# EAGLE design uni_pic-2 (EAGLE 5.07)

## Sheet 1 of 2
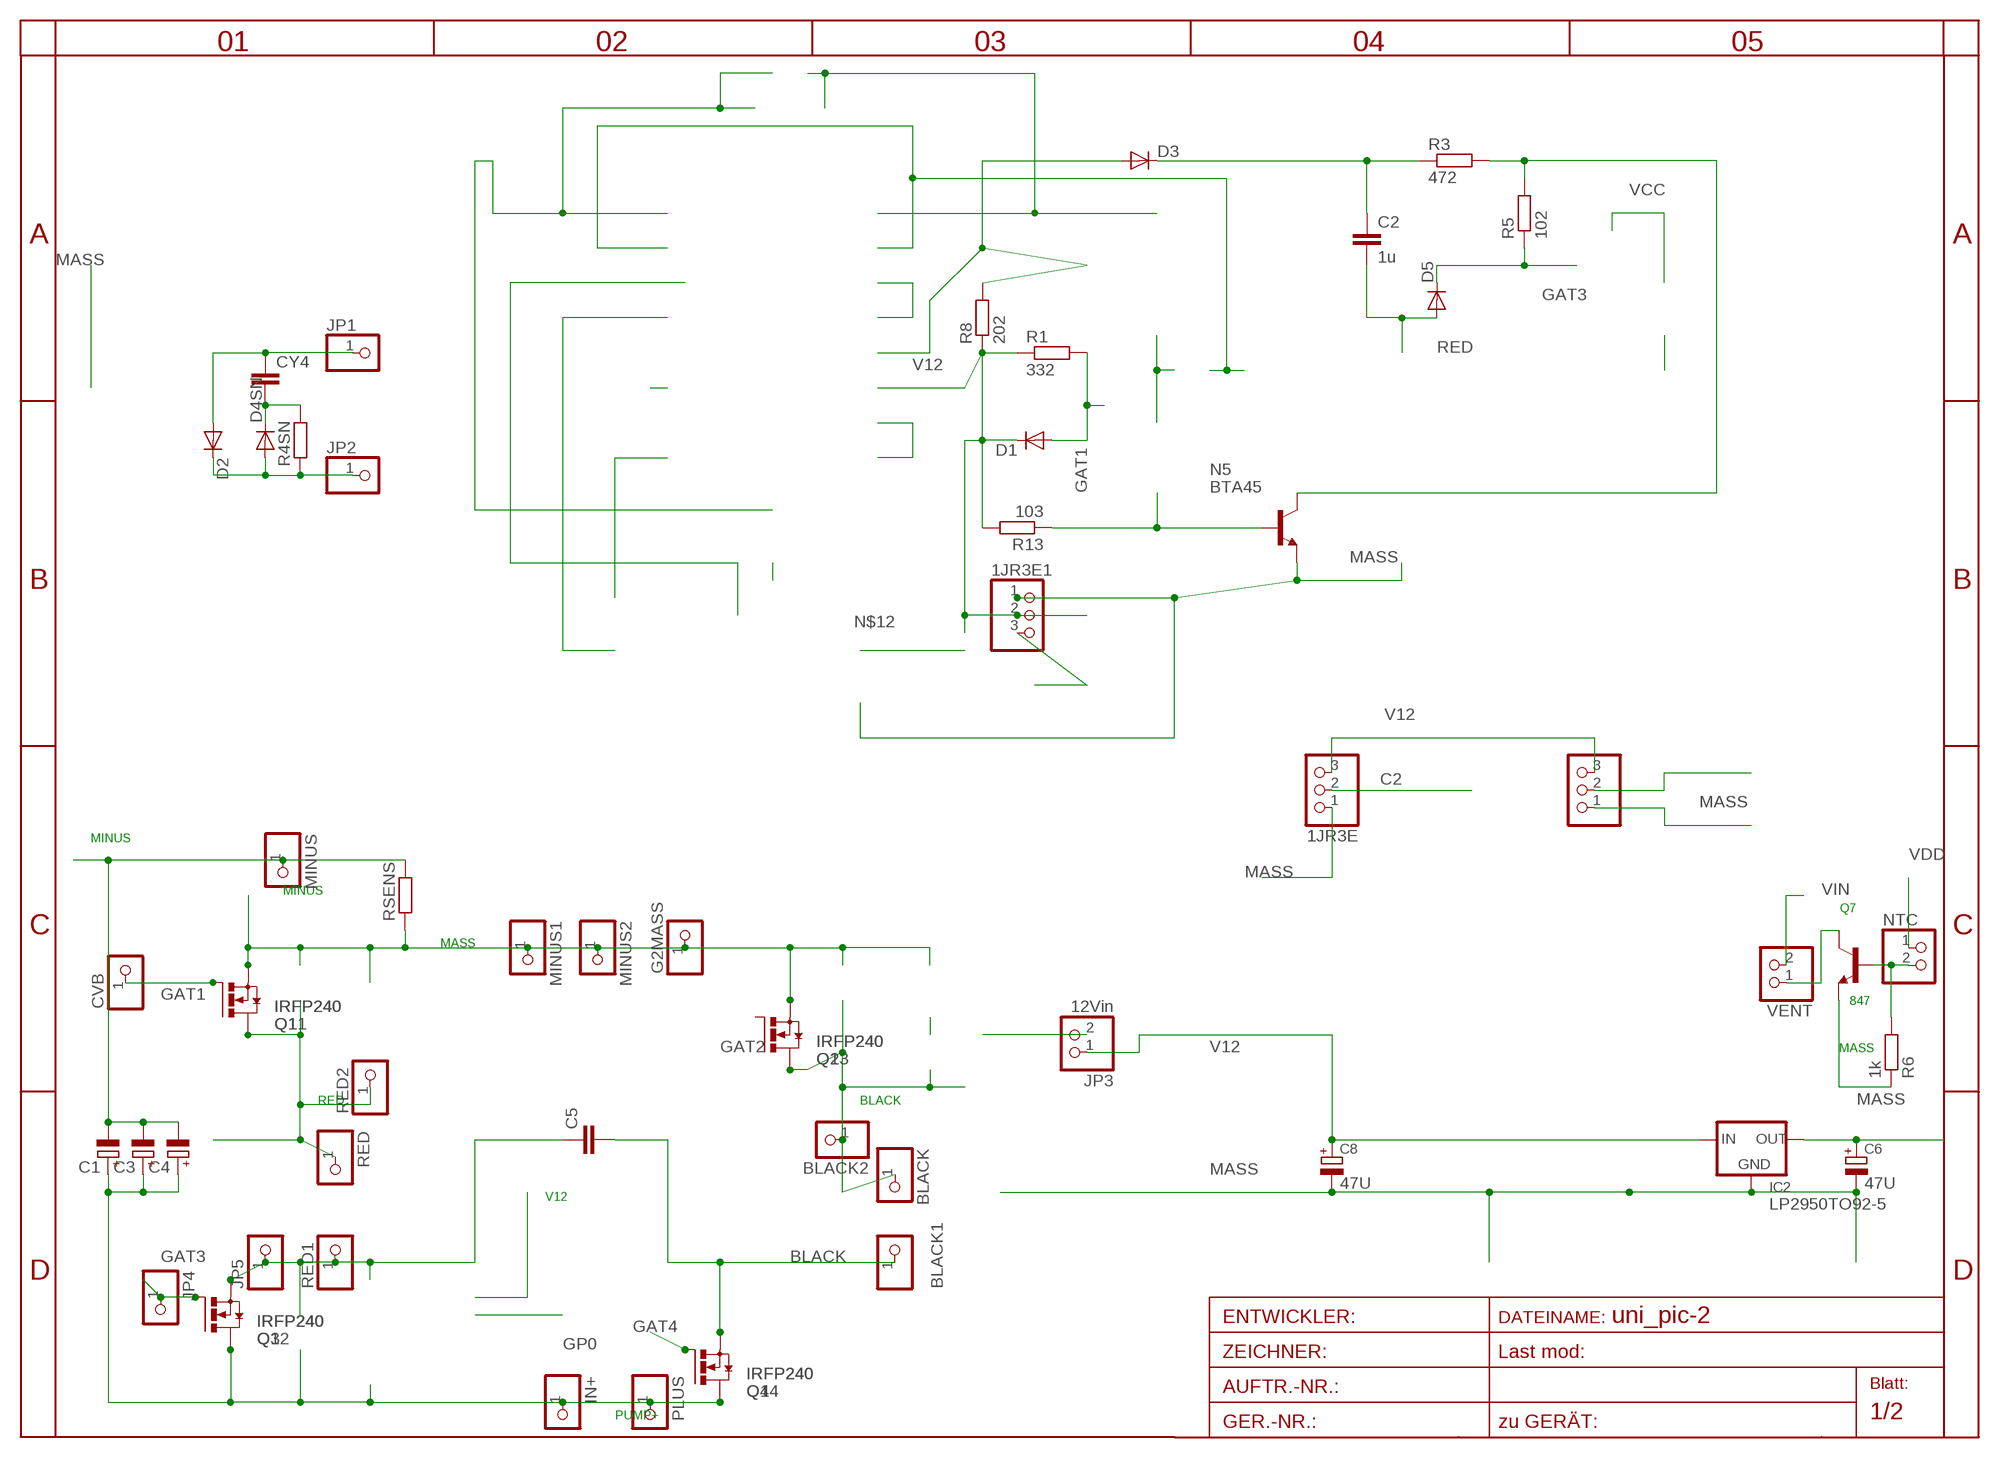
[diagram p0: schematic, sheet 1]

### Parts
1JR3E  PINHD-1X3  [1X03]
1JR3E1  PINHD-1X3  [1X03]
2JR4E3  PINHD-1X3  [1X03]
BLACK  PINHD-1X12MM3  [1X2MM3]
BLACK1  PINHD-1X12MM3  [1X2MM3]
BLACK2  PINHD-1X12MM3  [1X2MM3]
C1  CPOL-EUE5-13  [E5-13]
C2  1u  C-EUC1206  [C1206]
C3  CPOL-EUE5-13  [E5-13]
C4  CPOL-EUE5-13  [E5-13]
C5  C-EU075-032X103  [C075-032X103]
C6  47U  CPOL-EUE2.5-6  [E2,5-6]
C8  47U  CPOL-EUE2.5-6  [E2,5-6]
CVB  PINHD-1X11MM0  [1X1MM0]
CY4  CXXC10B5  [XC10B5]
D1  DIODE-MINIMELF  [MINIMELF]
D2  DIODE-SMC  [SMC]
D3  DIODE-SMA-DO214  [SMA-DO214AC]
D4SN  DIODE-P1-10  [P1-10]
D5  DIODE-MINIMELF  [MINIMELF]
G2MASS  PINHD-1X11MM0  [1X1MM0]
IC2  LP2950TO92-5  [T092-5]
IN+  PINHD-1X12MM3  [1X2MM3]
JP1  PINHD-1X11MM0  [1X1MM0]
JP2  PINHD-1X11MM0  [1X1MM0]
JP3  12Vin  PINHD-1X2STR  [1X02]
JP4  PINHD-1X11MM0  [1X1MM0]
JP5  PINHD-1X11MM0  [1X1MM0]
MINUS  PINHD-1X12MM3  [1X2MM3]
MINUS1  PINHD-1X12MM3  [1X2MM3]
MINUS2  PINHD-1X12MM3  [1X2MM3]
N5  BTA45  SMBTA45HV  [SOT23HV]
NTC  PINHD-1X2STR  [1X02]
PLUS  PINHD-1X12MM3  [1X2MM3]
Q1  IRFP240  [TO247BV]
Q2  IRFP240  [TO247BV]
Q3  IRFP240  [TO247BV]
Q4  IRFP240  [TO247BV]
Q7  847  BC847ALT1SMD  [SOT23]
Q11  IRFP240  [TO247BV]
Q12  IRFP240  [TO247BV]
Q13  IRFP240  [TO247BV]
Q14  IRFP240  [TO247BV]
R1  332  R-EU_R0805  [R0805]
R3  472  R-EU_R0805  [R0805]
R4SN  R-EU_0207/10  [0207/10]
R5  102  R-EU_R1206  [R1206]
R6  1k  R-EU_R0805  [R0805]
R8  202  R-EU_R0805  [R0805]
R13  103  R-EU_0207/15  [0207/15]
RED  PINHD-1X12MM3  [1X2MM3]
RED1  PINHD-1X12MM3  [1X2MM3]
RED2  PINHD-1X12MM3  [1X2MM3]
RSENS  R-EU_0204/7  [0204/7]
VENT  PINHD-1X2STR  [1X02]

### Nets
BLACK: BLACK1.1 BLACK2.1 BLACK.1 C5.2 Q2.D Q4.S Q13.D Q14.S
C1: 2JR4E3.2 ; also sheet 2
C2: 1JR3E1.2 1JR3E.2 D1.C R1.1 R8.1 R13.2 ; also sheet 2
DRAIN: D2.C D4SN.A JP2.1 R4SN.1
GAT1: CVB.1 D1.A Q1.G Q11.G R1.2
GAT2: Q2.G Q13.G
GAT3: D5.C JP4.1 Q3.G Q12.G R5.1
GAT4: Q4.G Q14.G
MASS: 1JR3E1.1 1JR3E.1 2JR4E3.1 C6.- C8.- G2MASS.1 IC2.2(GND) JP3.2 MINUS1.1 MINUS2.1 N5.2(E) Q1.S Q2.S Q7.2(E) Q11.S Q13.S R6.1 RSENS.1 ; also sheet 2
MINUS: C1.- C3.- C4.- MINUS.1 RSENS.2
N$4: C2.1 D3.K(C) R3.1
N$8: N5.3(C) R3.2 R5.2
N$9: NTC.2 Q7.1(B) R6.2
N$10: Q7.3(C) VENT.1
N$17: N5.1(B) R13.1
PUMP+: C1.+ C3.+ C4.+ IN+.1 PLUS.1 Q3.D Q4.D Q12.D Q14.D ; also sheet 2
RED: C2.2 C5.1 D5.A JP5.1 Q1.D Q3.S Q11.D Q12.S RED1.1 RED2.1 RED.1
SNUB2: CY4.2 D4SN.C R4SN.2
SOURCE: CY4.1 D2.A JP1.1
V12: 1JR3E1.3 1JR3E.3 2JR4E3.3 C8.+ D3.A IC2.3(IN) JP3.1 R8.2
VDD: C6.+ IC2.1(OUT) NTC.1 ; also sheet 2
VIN: VENT.2

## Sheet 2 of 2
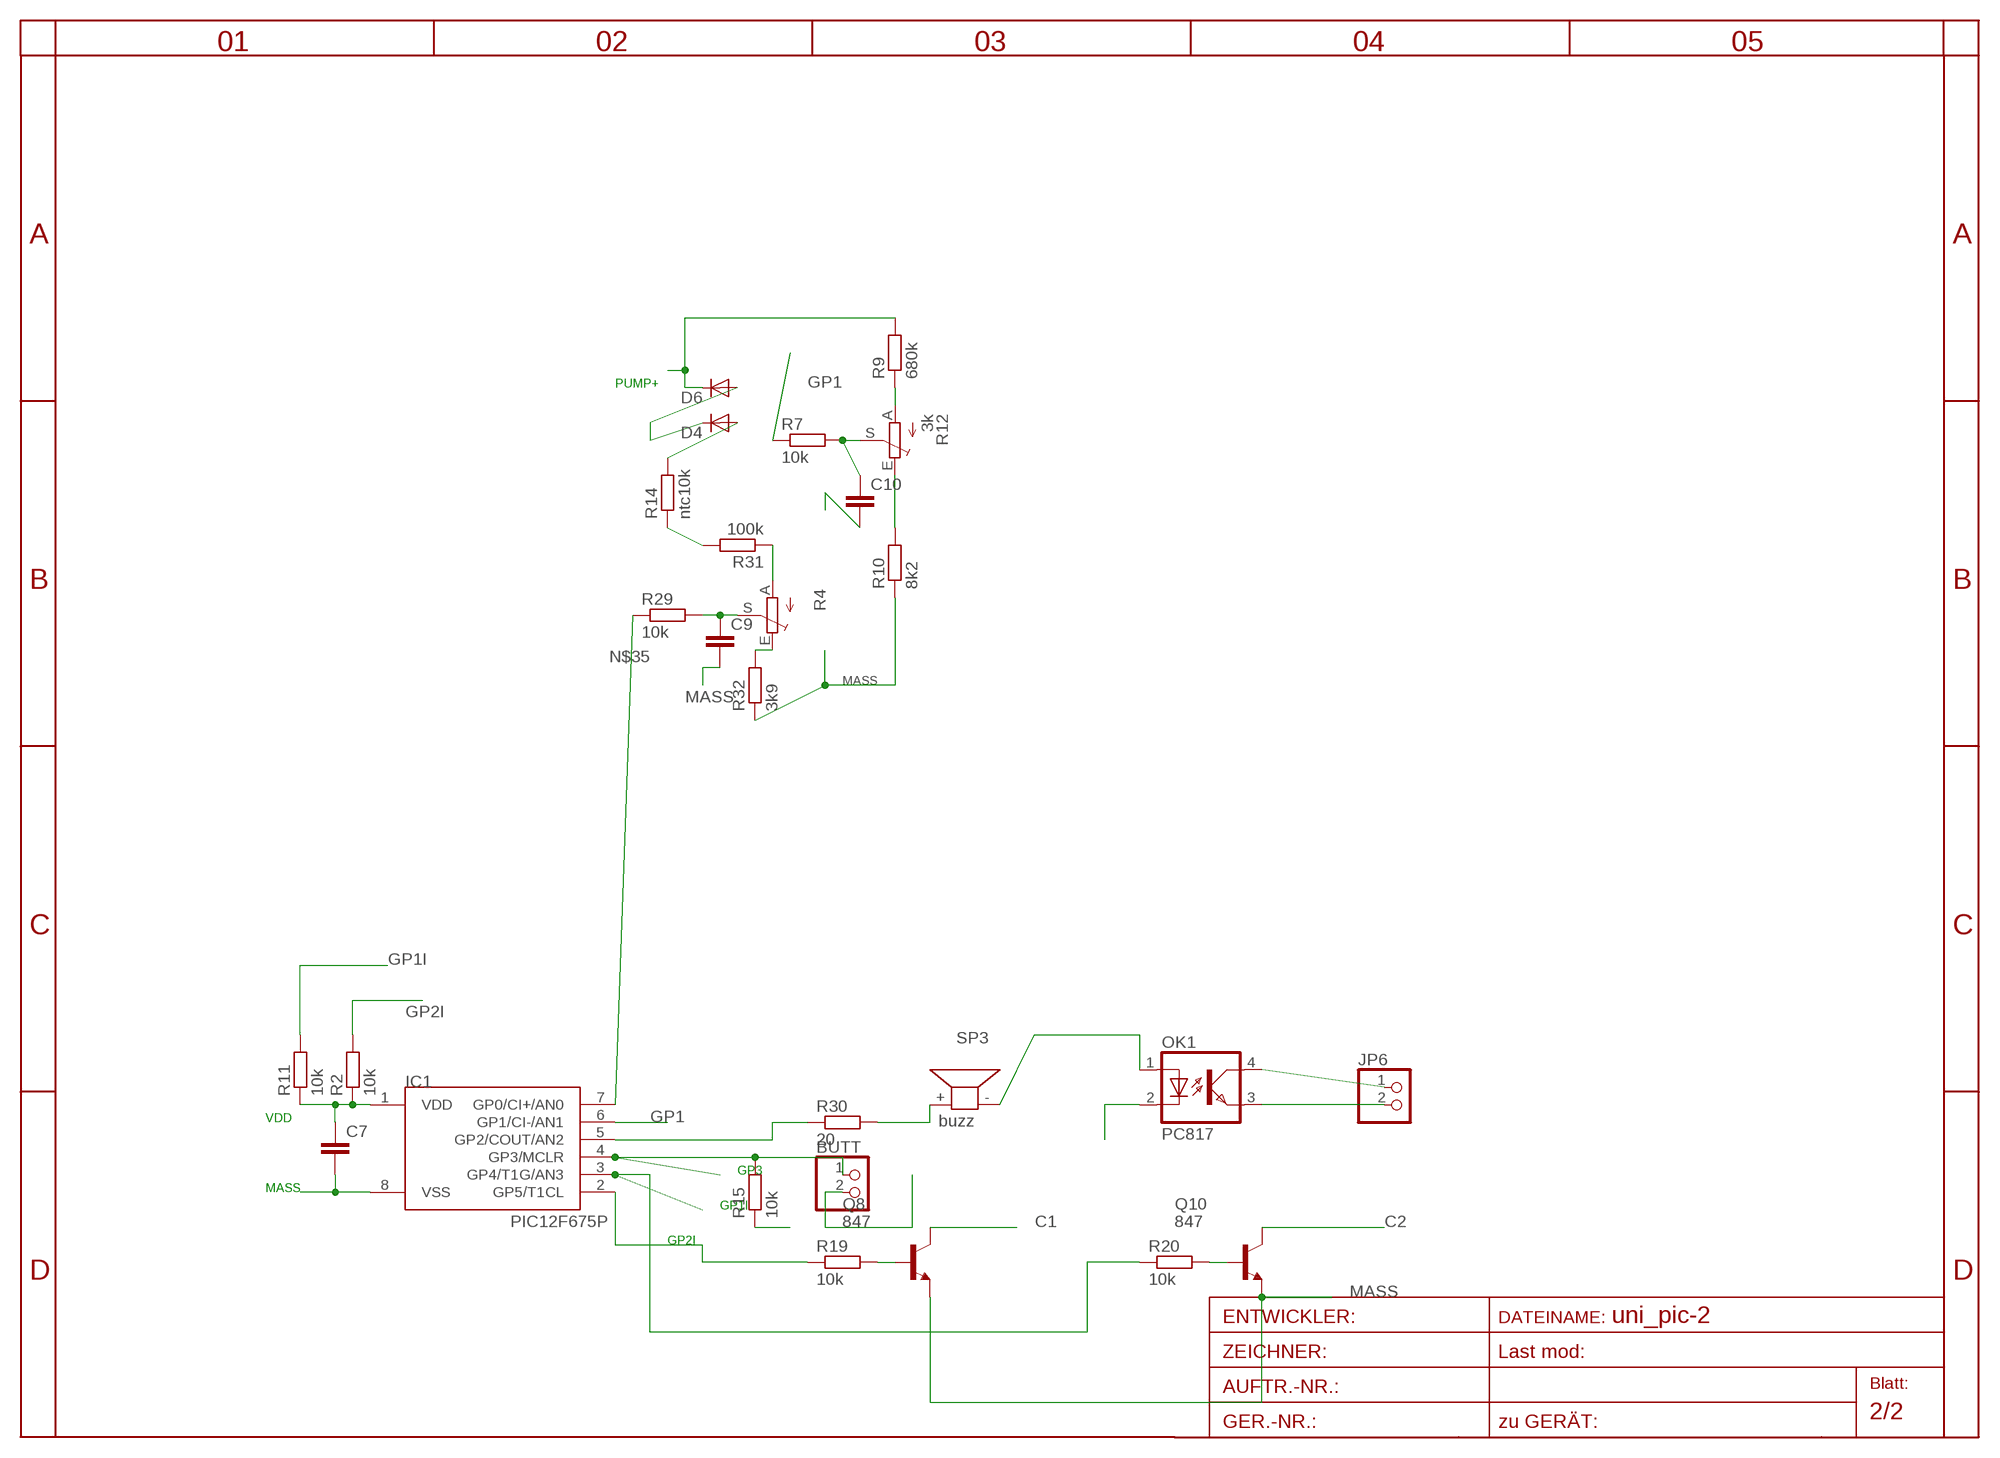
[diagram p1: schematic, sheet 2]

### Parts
BUTT  PINHD-1X2STR  [1X02]
C7  C-EUC0805  [C0805]
C9  C-EUC0805  [C0805]
C10  C-EUC0805  [C0805]
D4  DIODE-MINIMELF  [MINIMELF]
D6  DIODE-MINIMELF  [MINIMELF]
IC1  PIC12F675P  [DIL8]
JP6  PINHD-1X2STR  [1X02]
OK1  PC817  [DIL04]
Q8  847  BC847ALT1SMD  [SOT23]
Q10  847  BC847ALT1SMD  [SOT23]
R2  10k  R-EU_R0805  [R0805]
R4  TRIM_EU-CA6V  [CA6V]
R7  10k  R-EU_R0805  [R0805]
R9  680k  R-EU_0207/30  [0207/30]
R10  8k2  R-EU_R0805  [R0805]
R11  10k  R-EU_R0805  [R0805]
R12  3k  TRIM_EU-CA6V  [CA6V]
R14  ntc10k  R-EU_0204/5  [0204/5]
R15  10k  R-EU_R0805  [R0805]
R19  10k  R-EU_R0805  [R0805]
R20  10k  R-EU_R0805  [R0805]
R29  10k  R-EU_R0805  [R0805]
R30  20  R-EU_R0805  [R0805]
R31  100k  R-EU_0207/22  [0207/22]
R32  3k9  R-EU_R0805  [R0805]
SP3  buzz  KSS12017MM  [KSS1202]

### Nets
C1: Q8.3(C) ; also sheet 1
C2: Q10.3(C) ; also sheet 1
GP0I: IC1.5(GP2/COUT/AN2) R30.1
GP1: IC1.6(GP1/CI-/AN1) R7.1
GP1I: IC1.3(GP4/T1G/AN3) R11.2 R20.1
GP2I: IC1.2(GP5/T1CL) R2.2 R19.1
GP3: BUTT.1 IC1.4(GP3/MCLR) R15.2
MASS: BUTT.2 C7.2 C9.2 C10.2 IC1.8(VSS) OK1.2(C) Q8.2(E) Q10.2(E) R10.1 R32.1 ; also sheet 1
N$1: R4.A R31.1
N$5: JP6.2 OK1.3(EMIT)
N$7: D4.C D6.A
N$19: C9.1 R4.S R29.2
N$22: Q10.1(B) R20.2
N$24: R14.1 R31.2
N$26: R4.E R32.2
N$27: D4.A R14.2
N$28: Q8.1(B) R19.2
N$29: R10.2 R12.E
N$30: R9.1 R12.A
N$31: C10.1 R7.2 R12.S
N$32: JP6.1 OK1.4(COL)
N$33: R30.2 SP3.+
N$34: OK1.1(A) SP3.-
N$35: IC1.7(GP0/CI+/AN0) R29.1
PUMP+: D6.C R9.2 ; also sheet 1
VDD: C7.1 IC1.1(VDD) R2.1 R11.1 R15.1 ; also sheet 1

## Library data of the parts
1JR3E 1JR3E1 2JR4E3 = pinhead:PINHD-1X3: PIN HEADER
BLACK BLACK1 BLACK2 CVB G2MASS IN+ JP1 JP2 JP4 JP5 MINUS MINUS1 MINUS2 PLUS RED RED1 RED2 = pinhead:PINHD-1X1: PIN HEADER
BUTT JP3 JP6 NTC VENT = pinhead:PINHD-1X2: PIN HEADER
C1 C3 C4 = rcl:CPOL-EU: POLARIZED CAPACITOR, European symbol
C2 C5 C7 C9 C10 = rcl:C-EU: CAPACITOR, European symbol
C6 C8 = rcl-2:CPOL-EU: POLARIZED CAPACITOR, European symbol
CY4 = rcl:CX: X CAPACITOR
D1-D4 D4SN D5 D6 = diode:DIODE-: DIODE
IC1 = microchip-5:PIC12F6*: uPC nW 1k Program Flash memory 2x Timer Comparator 10b A/D converter/ 4xIN
IC2 = v-reg:LP2950?*: Source: http://cache.national.com/ds/LP/LP2950.pdf
N5 = transistor-npn:SMBTA45
OK1 = optocoupler:PC817: SHARP OPTO COUPLER
Q1-Q4 Q11-Q14 = transistor-power:IRFP240: HEXFET Power MosFet Source: http://www.irf.com/
Q7 Q8 Q10 = transistor-npn:BC847*: NPN Transistor
R1 R3 R4SN R5 R6 R8 R13 RSENS = rcl:R-EU_: RESISTOR, European symbol
R2 R7 R9-R11 R14 R15 R19 R20 R29-R32 = rcl-2:R-EU_: RESISTOR, European symbol
R4 R12 = pot:TRIM_EU-: POTENTIOMETER
SP3 = buzzer:KSS1201: SPEAKER

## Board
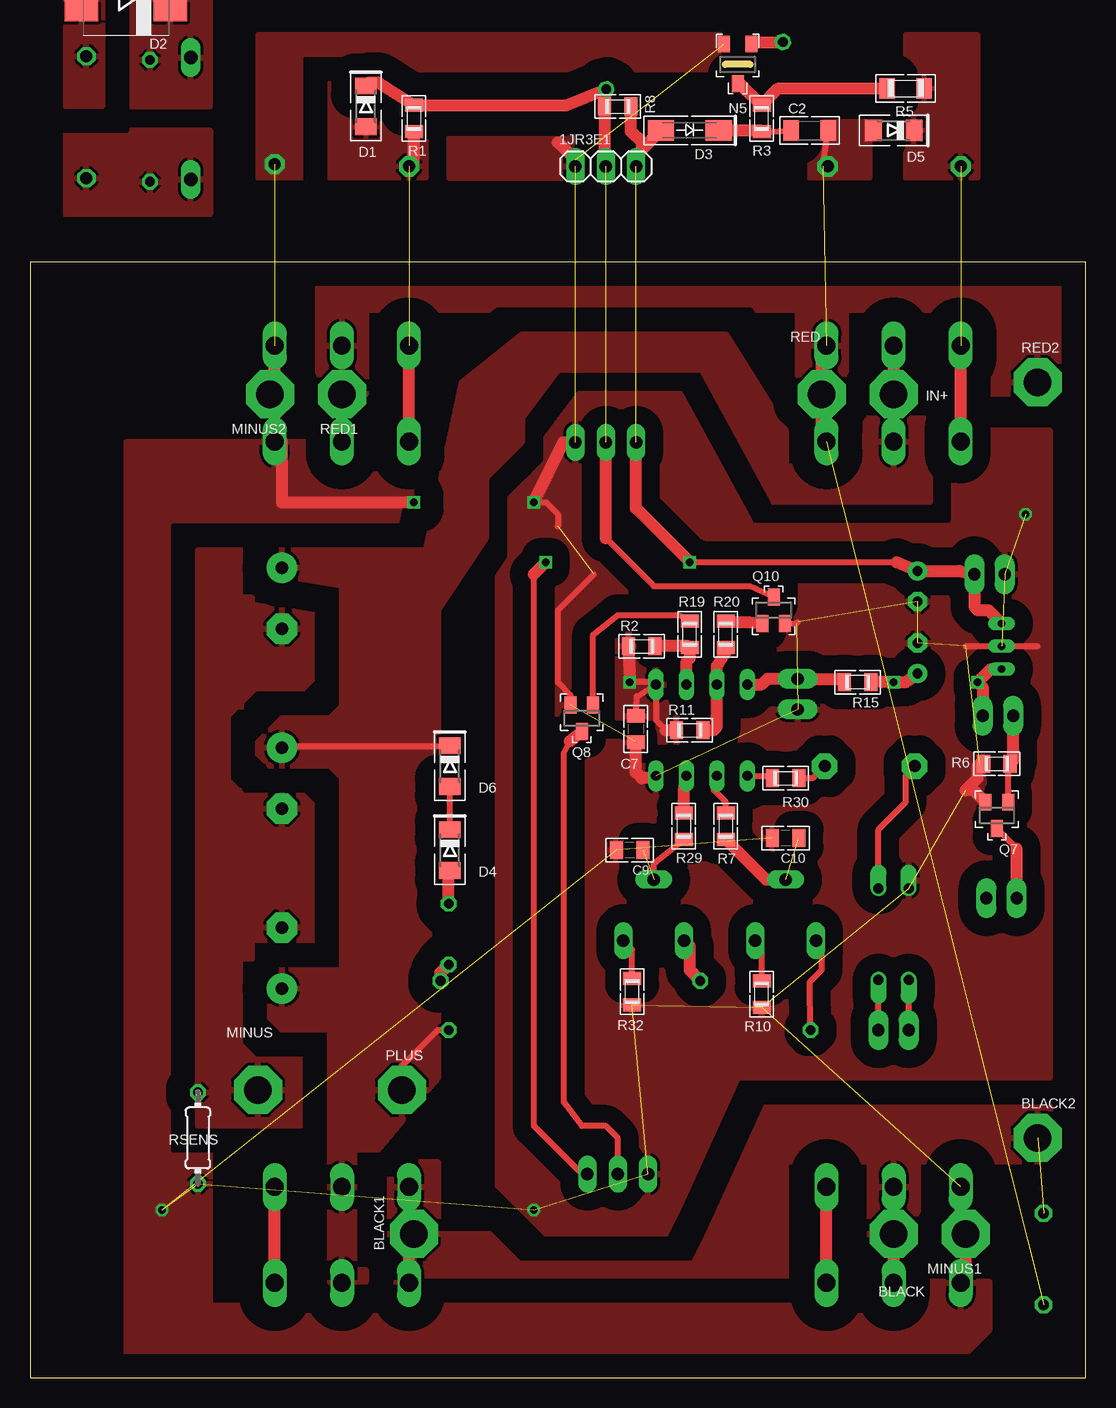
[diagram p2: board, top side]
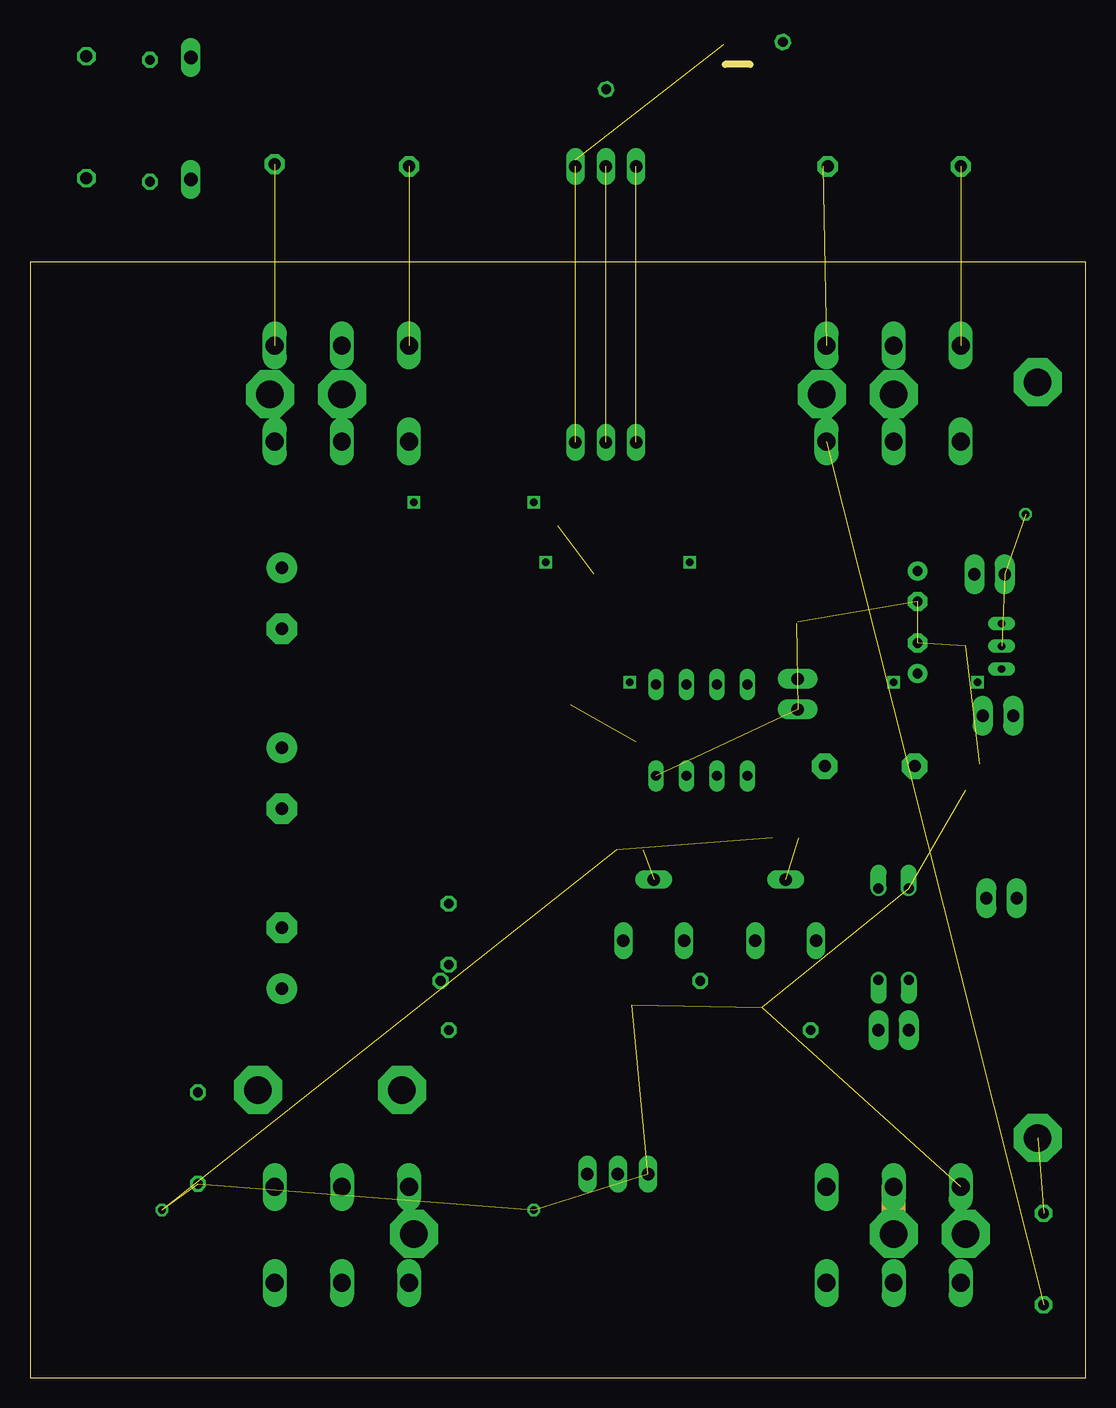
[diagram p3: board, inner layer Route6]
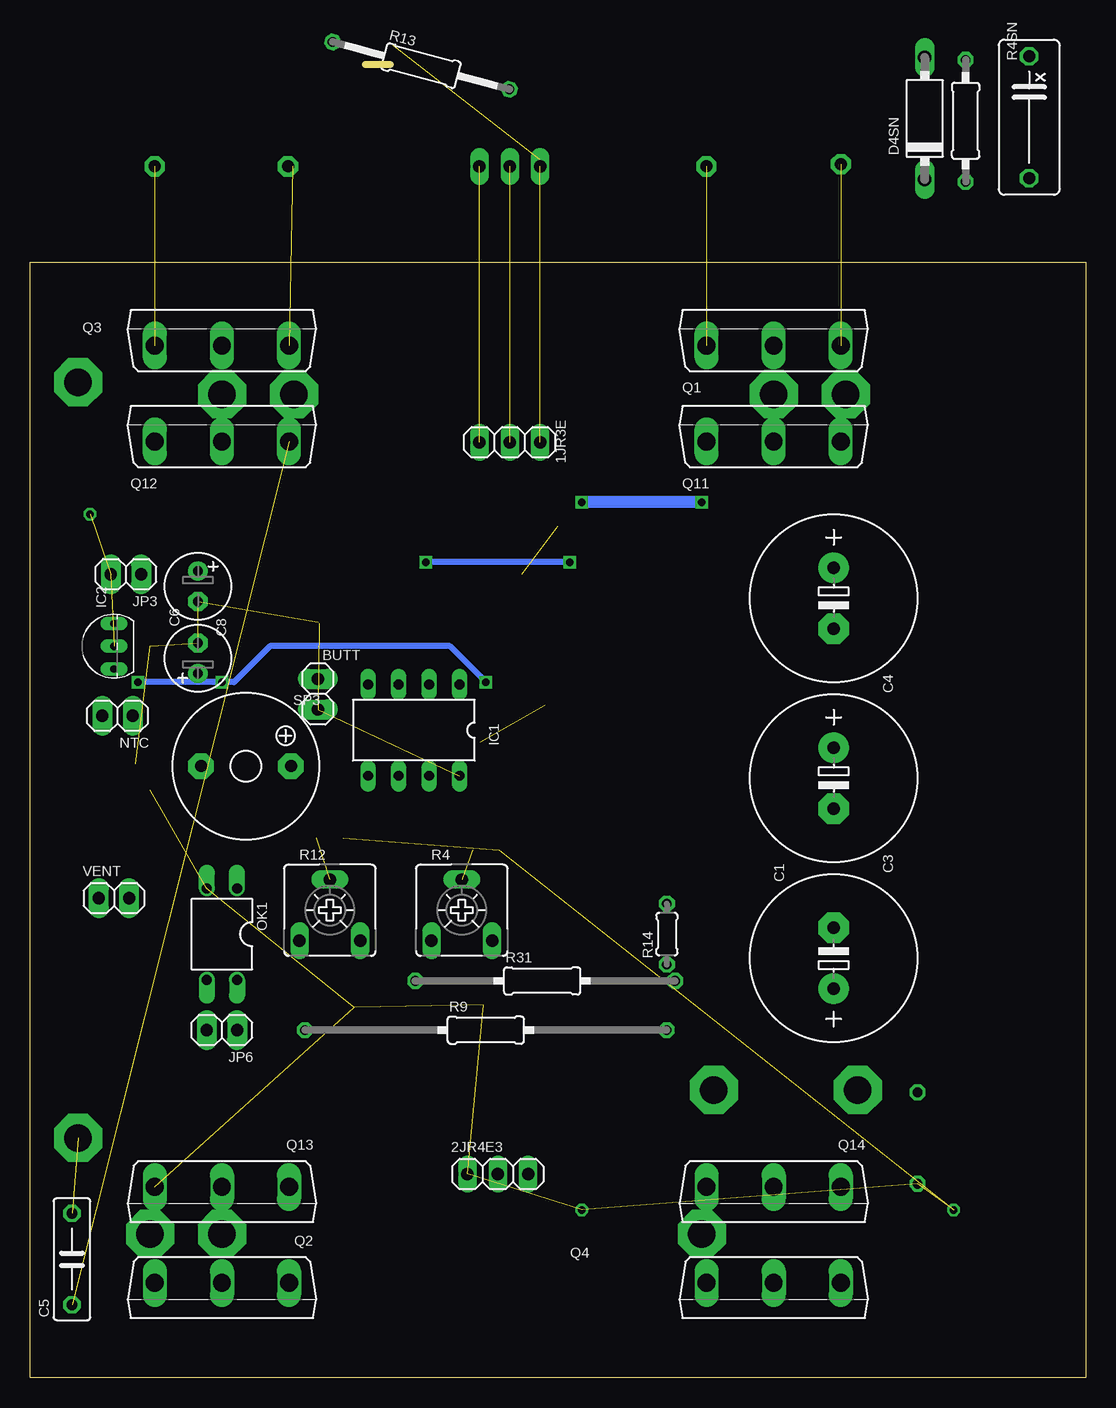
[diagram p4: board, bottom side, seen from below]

Size 88 x 93 mm. Coordinates in mm from the lower left corner, seen from the top.
Outline: 0,0 88,0 88,93 0,93 0,0
Copper layers (1*16): Top 0.035mm / dielectric 1.5mm / Bottom 0.035mm
Design rules "default *": minimum track width 10mil, minimum drill 20mil, track to track 8mil, track to pad 8mil, pad to pad 8mil, via to via 8mil, smd to smd 8mil, copper to edge 40mil, drill to drill 8mil, minimum pad ring 10mil, minimum via ring 8mil, stop-mask expansion 4mil, vias tented up to drill 0mil, thermal gap 10mil

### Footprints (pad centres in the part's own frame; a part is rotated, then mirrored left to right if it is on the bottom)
1X03 = drill 1.016 long: 1 -2.54,0; 2 0,0; 3 2.54,0
1X2MM3 = drill 2.3 pad 4 octagon: 1 0,0
1X02 = drill 1.016 pad 1.676 long: 1 -1.27,0; 2 1.27,0
E5-13 = drill 1.016 pad 2.54 round: + -2.54,0 | drill 1.016 pad 2.54 octagon: - 2.54,0
C1206 = smd 1.3 x 1.7: 1 -1.55,0; 2 1.55,0
C075-032X103 = drill 0.914 octagon: 1 -3.81,0; 2 3.81,0
E2,5-6 = drill 0.813 pad 1.6 round: + -1.27,0 | drill 0.813 pad 1.6 octagon: - 1.27,0
C0805 = smd 1.1 x 1.5: 1 -1.1,0; 2 1.1,0
1X1MM0 = drill 1 pad 1.676 octagon: 1 0,0
XC10B5 = drill 1.016 octagon: 1 -5.08,0; 2 5.08,0
MINIMELF = smd 1.4 x 1.8: A 1.7,0; C -1.7,0
SMC = smd 2.8 x 3.8: A 3.7,0; C -3.7,0
SMA-DO214AC = smd 2.2 x 1.7: A 2.4,0; K -2.4,0
P1-10 = drill 1.118 long: A 5.08,0; C -5.08,0
DIL8 = drill 0.8 long: 1 -3.81,-3.81; 2 -1.27,-3.81; 3 1.27,-3.81; 4 3.81,-3.81; 5 3.81,3.81; 6 1.27,3.81; 7 -1.27,3.81; 8 -3.81,3.81
T092-5 = drill 0.6 pad 0.813 long: 1 -1.905,0; 2 0,0; 3 1.905,0
SOT23HV = smd 1 x 1.4: 1 -1.15,-1.7; 2 1.15,-1.7; 3 0,1.6
DIL04 = drill 0.813 offset: 1 -1.27,-3.81; 2 1.27,-3.81; 3 1.27,3.81; 4 -1.27,3.81
TO247BV = drill 1.499 long: D 0,-2.921; G -5.588,-2.921; S 5.588,-2.921
SOT23 = smd 1 x 1.4: 1 -0.95,-1.1; 2 0.95,-1.1; 3 0,1.1
R0805 = smd 1.1 x 1.5: 1 -1.1,0; 2 1.1,0
CA6V = drill 1.016 long: A -2.54,-2.54; E 2.54,-2.54; S 0,2.54
0207/10 = drill 0.813 octagon: 1 -5.08,0; 2 5.08,0
R1206 = smd 1.3 x 1.7: 1 -1.55,0; 2 1.55,0
0207/30 = drill 0.813 octagon: 1 -15.08,0; 2 15.08,0
0207/15 = drill 0.813 octagon: 1 -7.62,0; 2 7.62,0
0204/5 = drill 0.8 pad 1.27 octagon: 1 -2.54,0; 2 2.54,0
0207/22 = drill 0.813 octagon: 1 -10.58,0; 2 11.08,0
0204/7 = drill 0.813 octagon: 1 -3.81,0; 2 3.81,0
KSS1202 = drill 1 pad 2.159 octagon: + 3.75,0; - -3.75,0

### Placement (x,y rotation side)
1JR3E  48,78 180 bottom
1JR3E1  48,101 0 top  (outside the outline)
2JR4E3  49,17 0 bottom
BLACK  72,12 180 top
BLACK1  32,12 90 top
BLACK2  84,20 0 top
BUTT  64,57 270 bottom
C1  21,35 90 bottom
C2  65,104 0 top  (outside the outline)
C3  21,50 270 bottom
C4  21,65 270 bottom
C5  84.5,9.9 90 bottom
C6  74,60 90 bottom
C7  50.5,54.1 270 top
C8  74,66 270 bottom
C9  50,44 180 top
C10  63,45 180 top
CVB  31.6,101 0 top  (outside the outline)
CY4  not placed on the board
D1  28,106 270 top  (outside the outline)
D2  not placed on the board
D3  55,104 180 top  (outside the outline)
D4  35,44 270 top
D4SN  not placed on the board
D5  not placed on the board
D6  35,51 270 top
G2MASS  not placed on the board
IC1  56,54 180 bottom
IC2  81,61 90 bottom
IN+  72,82 0 top
JP1  not placed on the board
JP2  not placed on the board
JP3  80,67 180 bottom
JP4  not placed on the board
JP5  66.5,101 180 top  (outside the outline)
JP6  72,29 180 bottom
MINUS  19,24 0 top
MINUS1  78,12 180 top
MINUS2  20,82 180 top
N5  59,109.5 180 top  (outside the outline)
NTC  80.7,55.2 180 bottom
OK1  72,37 180 bottom
PLUS  31,24 0 top
Q1  26,89 0 bottom
Q2  72,5 180 bottom
Q3  72,89 0 bottom
Q4  26,5 180 bottom
Q7  80.6,46.9 180 top
Q8  46,55 180 top
Q10  62,64 0 top
Q11  26,81 0 bottom
Q12  72,81 0 bottom
Q13  72,13 180 bottom
Q14  26,13 180 bottom
R1  32,105 270 top  (outside the outline)
R2  51,61 0 top
R3  61,105 90 top  (outside the outline)
R4  52,39 0 bottom
R4SN  not placed on the board
R5  73,107.5 180 top  (outside the outline)
R6  80.6,51.2 0 top
R7  58,46 270 top
R8  49,106 0 top  (outside the outline)
R9  50,29 0 bottom
R10  61,32 90 top
R11  55,54 0 top
R12  63,39 0 bottom
R13  55.4,109.4 345 bottom  (outside the outline)
R14  34.9,37 90 bottom
R15  69,58 180 top
R19  55,62 90 top
R20  58,62 90 top
R29  54.5,46 270 top
R30  63,50 0 top
R31  45.3,33.1 0 bottom
R32  50.2,32.2 90 top
RED  66,82 0 top
RED1  26,82 180 top
RED2  84,83 0 top
RSENS  14,20 90 top
SP3  70,51 0 bottom
VENT  81,40 0 bottom

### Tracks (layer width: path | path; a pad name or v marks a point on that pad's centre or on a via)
BLACK  (1 unrouted)
  Top 1: Q14.S 31.59,11.41 32,11 BLACK1.1 31.59,11.59 Q4.S | Q2.D BLACK.1
  Route6 2: BLACK.1 Q13.D
  pour Top (isolate 2, rank 4): 30,18 34,18 34,12 55,12 61,24 85,24 85,18 74,18 74,10 70,10 70,18 63,18 63,8 30,8
C1
  Top 0.5: 2JR4E3.2 49,20 48,21 46,21 44.5,23 44.5,52.1 45,53.1
  Top 1.016: 45,53.1 Q8.3
C2  (1 unrouted)
  Top 0.5: Q10.3 60,66 52,66 48,70
  Top 1: D1.C 28.3,108 29,108 R1.1 44.71,106.1 R13.2 47.9,107 R8.1 47.9,101.1 1JR3E1.2
  Top 1.016: 48,70 1JR3E.2
DRAIN
  pour Top (isolate 2, rank 2): 8,120 8,106 15,106 15,120
GAT1  (1 unrouted)
  Top 1: R1.2 32,101.4 CVB.1
  Top 1.016: Q11.G Q1.G
  pour Top (isolate 2): 25,100 25,108 33,108 33,100
GAT2
  Top 1: Q2.G Q13.G
GAT3  (1 unrouted)
  Top 1.016: Q12.G Q3.G
  pour Top (isolate 2, rank 2): 73,112 79,112 79,100 73,100
GAT4
  Top 1: Q4.G Q14.G
GP0I
  Top 0.5: IC1.5 61.71,50.19 R30.1
GP1
  Top 0.5: R7.1 58,48 57,49 57,49.92 IC1.6
GP1I
  Top 1: R20.1 58,60.5 57.27,59.33 IC1.3 57.27,54.27 57,54 R11.2
GP2I
  Top 1: IC1.2 54.73,59.73 55,60 R19.1 54.9,61 R2.2
GP3
  Top 1: IC1.4 61.01,57.81 61.5,58.3 63.97,58.3 BUTT.1 67.63,58.27 R15.2
MASS  (via drill 0.6)  (23 unrouted)
  Top 0.5: 78,61 IC2.2 84,61 | Q10.2 63.9,62.9 64,63 | Q8.2 45.05,56.95 44,58 44,64 47,67 | 44,71 44,72 43,73 v42,73
  Top 1: C7.2 50.5,50.5 51,50 52,50 IC1.8 | Q13.S 77.59,11.41 MINUS1.1 78,8.33 Q2.S | 1JR3E1.1 45.46,101.54 44,103 | R6.1 79.2,51.2 79,51 79,50 78,49 78.65,49 Q7.2
  Top 1.016: 20.41,83 Q1.S | 20.41,83 MINUS2.1 | 20.41,83 Q11.S 21,78.08 21,73 v32,73 | 1JR3E.1 44.46,78 v42,73
  Bottom 1.016: v32,73 v42,73
  other vias: 83,72 42,14 11,14
  pour Top (isolate 1.5, rank 3): 39,16 39,77 44,83 54,83 55,82 56,79 85,79 85,25 59,25 54,14 53,12 43,12
  pour Top (isolate 2, rank 2, no thermals): 19,112 65,112 65,109 23,109 23,100 19,100
  pour Top (isolate 2, rank 3): 34,78 8,78 8,2 12,0 72,0 74,2 78,2 80,4 80,8 73,8 73,6 15,6 15,69 32,68
  pour Top (isolate 2): 35,105 46,105 46,100 35,100
MINUS
  pour Top (isolate 2, rank 2): 14,69 24,69 24,21 14,21
N$1
  Top 1: R31.1 55.88,33.12 55,34 55,36 R4.A
N$4
  Top 0.5: C2.1 61.8,103.9 R3.1
  Top 1: D3.K 60.9,104 R3.1
N$5
  Top 0.5: JP6.2 OK1.3
N$7
  Top 0.5: D4.C D6.A
N$8
  Top 1: R5.2 62.4,107.5 R3.2 59.2,107.9 N5.3
N$9
  Top 0.5: 81.97,51.47 R6.2 81.55,51.05 Q7.1
  Top 1: 81.97,51.47 NTC.2
N$10
  Top 0.5: 82.27,44.13 Q7.3
  Top 1: VENT.1 82.27,44.13
N$17
  Top 1: R13.1 60.32,111.37 N5.1
N$19  (1 unrouted)
  Top 0.5: R4.S 52,42.9 R29.2
N$22
  Top 1: R20.2 59,63 59.95,63 Q10.1
N$24
  Top 1: R31.2 34.22,33.78 R14.1
N$26
  Top 0.5: R32.2 50.2,35.72 R4.E
N$27
  Top 1: R14.2 34.9,42.2 D4.A
N$28
  Top 0.5: Q8.1 46.95,61.95 49,63.6 54.1,63.6 R19.2
N$29
  Top 0.5: R10.2 61,35.92 R12.E
N$30
  Top 0.5: R9.1 65,33 66,34 66,36 R12.A
N$31  (1 unrouted)
  Top 1: R12.S 61.36,41.54 R7.2
N$32
  Top 0.5: JP6.1 OK1.4
N$33
  Top 0.5: R30.2 65.25,50 SP3.+
N$34
  Top 0.5: OK1.1 70.73,45.73 73,48 73,50.25 SP3.-
N$35
  Top 1: R29.1 54.5,48.96 IC1.7
PUMP+
  Top 0.5: D6.C 21.16,52.7 C3.+ | R9.2 34,29 30,25 PLUS.1
  Top 1: Q3.D IN+.1 Q12.D
  pour Top (isolate 2): 26,66 20,67 20,69 33,69 36,83 41,87 58,87 63,79 63,76 69,76 69,80 75,80 75,73 62,73 56,84 44,84 41,80 41,78 38,75 38,70 34,64 34,25 29,19 27,19 27,9 28,9 28,8 25,8 25,29 21,29 20,30 20,34 26,34 26,50 25,51 20,51 19,52 19,53 21,55 25,55 26,56
RED  (2 unrouted)
  Top 0.5: C2.2 66.1,101 JP5.1 67,101
  Top 1: RED.1 66,85.67 Q3.S | Q11.D RED1.1 26,83
  Top 1.016: Q12.S 66,78.08 RED.1
  pour Top (isolate 2, no thermals): 65,105 70,105 70,100 65,100
  pour Top (isolate 2, rank 4): 28,82 24,82 24,93 86,93 86,82 80,82 80,89 68,89 68,81 64,81 64,89 28,89
SNUB2
  pour Top (isolate 2, rank 2): 3,104 15,104 15,97 3,97
SOURCE
  pour Top (isolate 2): 3,120 6,120 6,106 3,106
V12  (via drill 0.6)  (1 unrouted)
  Top 0.5: 2JR4E3.3 46,17 42,21 42,67 | v55,68 72.27,68
  Top 1: v55,68 50.5,72.5 50.5,77.96 1JR3E.3 | 72.27,68 C8.+ 77.46,67.27 JP3.1 78.73,64.27 79,64 79.91,64 IC2.3 | 42,67 v43,68 | 1JR3E1.3 50.54,101.94 51,102.4 | 51,102.4 D3.A | R8.2 50.1,103.9 51,103 51,102.4
  Bottom 0.5: v43,68 v55,68
VDD  (via drill 0.6)
  Top 0.5: 53,54 52.19,54.81 IC1.1 | v50,58 52,58 IC1.1 | 80.09,59.09 IC2.1 | C7.1 50.6,56.82 IC1.1
  Top 1: 53,54 R11.1 | v50,58 50,58.9 R2.1 | C6.+ 73,58 v72,58 71,58 70.1,58.1 R15.1 | 80.09,59.09 v79,58 79.43,57.57 NTC.1
  Bottom 0.5: v50,58 53,61 68,61 71,58 v72,58 v79,58
  pour Top (isolate 1.016): 49,62 51,62 51,59 53,59 53,55 54,55 54,53 52.4,53 52.4,55 49,55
